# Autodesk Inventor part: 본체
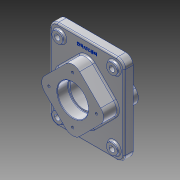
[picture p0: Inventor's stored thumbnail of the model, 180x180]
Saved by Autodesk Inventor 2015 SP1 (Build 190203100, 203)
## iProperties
Created: 2026-07
Part Number: 본체
Material: 알루미늄 6061
Document SubType Name: Modeling
Designer: user
Density: 2.7 g/cm^3
Appearance: 알루미늄 - 평지
Mass: 2132.41 g
Surface Area: 955.114 cm^2
Volume: 789.782 cm^3
Author: user
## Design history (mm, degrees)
sketch "스케치1"
  geometry: L1 (75, 90)-(-75, 90); L2 (-75, 90)-(-75, -90); L3 (-75, -90)-(75, -90); L4 (75, -90)-(75, 90); L5 (75, 90)-(-75, -90); L6 (-75, 90)-(75, -90); L7 (0, -70.711)-(-70.711, 0); L8 (-70.711, 0)-(0, 70.711); L9 (0, 70.711)-(70.711, 0); L10 (70.711, 0)-(0, -70.711); 3 further points
  constraints: 20 end point, 3 midpoint, 2 parallel, 1 coincident, 1 horizontal, 1 perpendicular, 1 vertical alignment, 9 other
  dimensions: "d0" = 150 distance of L3.end L2.end; "d1" = 180 distance of L2.end L1.end; "d2" = 100 distance between parallel lines of L7 L9
extrude "돌출1" new body sketch "스케치1" stored distance "d3" = 18; taper "d4" = 0 deg
extrude "돌출2" join sketch "스케치1" distance "d5" = 32; taper "d7" = 0 deg; dims "d6" = 38, "d8" = 0
fillet "모깎기1" dims "d9" = 20
fillet "모깎기2" dims "d10" = 20
fillet "모깎기3" dims "d11" = 15
sketch "스케치2"
  geometry: L1 (-75, 75)-(-75, -75) reference; L2 (-60, -90)-(60, -90) reference; C1 r 11 at (-55, -70); 1 further point
  constraints: 1 centre point
  dimensions: "d12" = 22 diameter of C1; "d13" = 20 distance from line of C1.centre L1; "d14" = 20 distance from line of L2 C1.centre
extrude "돌출3" join sketch "스케치2" distance "d15" = 5; taper "d16" = 0 deg
hole "구멍1" diameter "d19" = 11; stored, may be unused: countersink angle "d23" = 90 deg, drill point angle "d25" = 118 deg; dims "d17" = 10, "d18" = 10, "d20" = 6, "d21" = 4, "d22" = 2, "d24" = 8
sketch "스케치3"
  geometry: C1 r 31 at (0, 0); 1 further point
  constraints: 1 centre point, 1 coincident
  dimensions: "d32" = 62 diameter of C1
extrude "돌출4" cut sketch "스케치3" distance "d33" = 22; taper "d34" = 0 deg
hole "구멍2" diameter "d37" = 54; stored, may be unused: countersink angle "d41" = 90 deg, drill point angle "d43" = 118 deg; dims "d35" = 10, "d36" = 10, "d38" = 6, "d39" = 4, "d40" = 2, "d42" = 8
hole "구멍3" diameter "d46" = 62; stored, may be unused: countersink angle "d50" = 90 deg, drill point angle "d52" = 0 deg; dims "d44" = 10, "d45" = 10, "d47" = 6, "d48" = 4, "d49" = 2, "d51" = 22
sketch "스케치4"
  geometry: L1 (0, 0)-(0, 48)
  constraints: 2 end point, 1 vertical
  dimensions: "d53" = 48 distance of L1.start L1.end
hole "구멍4" sketch "스케치4" at (0, 48) diameter "d54" = 4.917; stored, may be unused: countersink angle "d58" = 90 deg, drill point angle "d60" = 118 deg; dims "d55" = 10, "d56" = 4, "d57" = 2, "d59" = 13
sketch "스케치5"
  geometry: L1 (0, 0)-(0, -48)
  constraints: 2 end point, 1 vertical
  dimensions: "d64" = 48 distance of L1.start L1.end
hole "구멍5" sketch "스케치5" at (0, -48) diameter "d65" = 4.917; stored, may be unused: countersink angle "d69" = 90 deg, drill point angle "d71" = 118 deg; dims "d66" = 10, "d67" = 4, "d68" = 2, "d70" = 13
sketch "스케치6"
  geometry: L1 (60, 90)-(-60, 90) reference; 2 further points
  constraints: 1 vertical alignment, 1 other
  dimensions: "d75" = 15 distance from line of point (0, 75) L1
feature "엠보싱1" sketch "스케치6" dims "d0" = 150, "d1" = 180, "d2" = 100, "d10" = 20, "d76" = 0.5, "d77" = 0
chamfer "모따기1" distance "d78" = 1; stored, may be unused: second distance "d79" = 2, angle "d80" = 45 deg
chamfer "모따기2" distance "d81" = 1; stored, may be unused: second distance "d82" = 2, angle "d83" = 45 deg
fillet "모깎기4" dims "d84" = 1
fillet "모깎기5" dims "d85" = 3
fillet "모깎기6" dims "d86" = 3
fillet "모깎기7" dims "d87" = 3
fillet "모깎기8" dims "d88" = 3
node "솔리드1"
pattern_linear "직사각형 패턴1"
pattern_circular "원형 패턴1" dims angle "d62" = 360 deg
pattern_circular "원형 패턴2" dims angle "d73" = 360 deg
